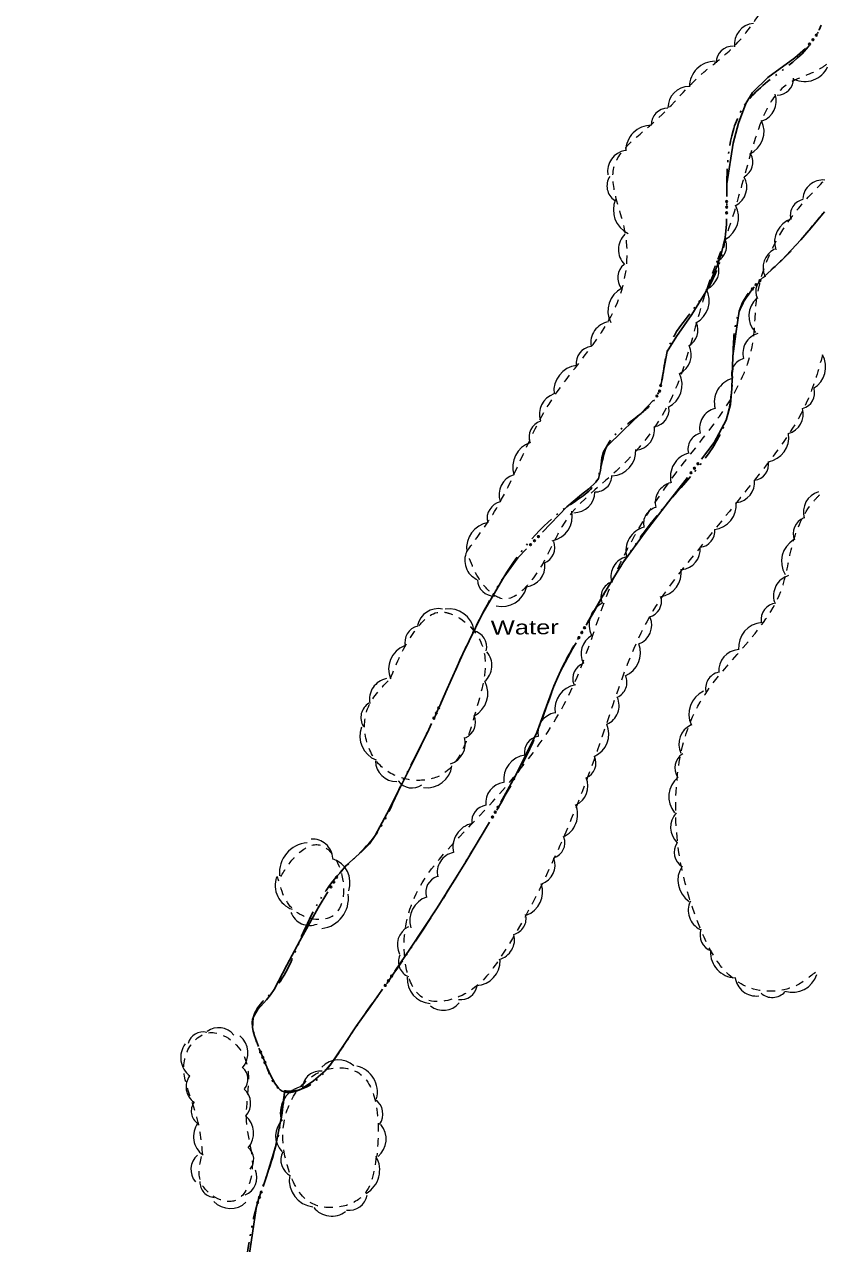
# Model space of a CAD drawing. Extents: x 2362213 to 2366494, y 6968794 to 6978110.
# Drawn here: x 2364792.2 to 2365065, y 6975207 to 6975621.3 of the extents above; entities that cross this region are included whole.
import ezdxf

# ---------------------------------------------------------------- set-up
doc = ezdxf.new("R2010")
doc.units = 0
doc.header["$LTSCALE"] = 1.9
doc.linetypes.add('DASH_DOUBLE_DOT', pattern=[9.2, 5, -1.2, 0.3, -1.2, 0.3, -1.2])
doc.linetypes.add('SHORT_DASHED', pattern=[2.7, 1.5, -1.2])
doc.layers.add('25', color=7, linetype='Continuous', lineweight=25)
doc.layers.add('29', color=7, linetype='Continuous', lineweight=13)

msp = doc.modelspace()

# ---------------------------------------------------------------- linework, layer by layer
at = {"layer": '25'}
for points in [[(2365062.159, 6975619.386), (2365062.179, 6975619.426), (2365062.824, 6975621.003)], [(2365030.754, 6975563.124), (2365030.785, 6975567.134), (2365032.914, 6975580.986), (2365034.719, 6975587.782), (2365037.275, 6975594.467), (2365039.461, 6975598.109), (2365044.721, 6975603.279), (2365053.929, 6975609.927), (2365057.559, 6975613.081)], [(2365063.918, 6975557.58), (2365059.963, 6975552.822), (2365055.907, 6975548.132), (2365052.74, 6975544.652), (2365049.512, 6975541.241), (2365045.805, 6975537.747), (2365043.516, 6975535.635)], [(2365008.698, 6975500.561), (2365010.567, 6975510.18), (2365013.638, 6975515.299), (2365018.948, 6975522.669), (2365023.703, 6975530.446), (2365027.589, 6975539.453), (2365029.115, 6975544.087), (2365030.22, 6975548.838), (2365030.676, 6975553.383), (2365030.688, 6975555.284)], [(2365038.15, 6975529.923), (2365037.734, 6975529.459), (2365036.07, 6975526.762), (2365035.028, 6975523.802), (2365033.801, 6975516.201), (2365032.883, 6975508.582), (2365032.438, 6975497.607), (2365031.979, 6975492.153), (2365030.53, 6975486.829), (2365026.542, 6975479.19), (2365022.186, 6975473.578)], [(2364968.18, 6975448.702), (2364976.487, 6975457.332), (2364981.428, 6975461.509), (2364983.96, 6975463.534), (2364986.299, 6975465.747), (2364987.147, 6975467.015), (2364987.871, 6975469.672), (2364988.35, 6975474.016), (2364988.871, 6975476.021), (2364989.925, 6975477.711), (2364995.562, 6975483.255), (2365001.239, 6975488.76), (2365004.092, 6975491.677), (2365005.755, 6975493.523)], [(2365017.385, 6975467.383), (2365010.924, 6975459.04), (2365003.08, 6975448.755), (2364995.481, 6975438.302), (2364988.882, 6975427.569), (2364983.443, 6975418.016)], [(2364933.728, 6975390.882), (2364935.394, 6975394.538), (2364941.102, 6975407.393), (2364947.566, 6975420.676), (2364954.993, 6975433.506), (2364959.782, 6975439.982), (2364962.744, 6975443.051)], [(2364979.567, 6975411.199), (2364978.387, 6975409.128), (2364974.299, 6975401.569), (2364972.048, 6975396.457), (2364966.278, 6975380.661), (2364959.182, 6975366.413), (2364954.022, 6975357.033)], [(2364899.448, 6975333.103), (2364901.544, 6975335.653), (2364906.879, 6975340.384), (2364909.374, 6975342.878), (2364911.387, 6975345.727), (2364915.258, 6975353.005), (2364918.989, 6975360.36), (2364924.308, 6975371.041), (2364929.566, 6975381.752), (2364930.476, 6975383.75)], [(2364950.157, 6975350.206), (2364942.136, 6975336.679), (2364932.402, 6975321.126), (2364923.393, 6975307.43), (2364918.028, 6975299.548)], [(2364871.699, 6975273.966), (2364870.354, 6975277.603), (2364869.879, 6975279.199), (2364869.637, 6975280.436), (2364869.569, 6975282.306), (2364869.711, 6975283.207), (2364870.003, 6975284.069), (2364871.499, 6975286.534), (2364874.379, 6975289.852), (2364875.783, 6975291.536), (2364876.975, 6975293.347), (2364881.327, 6975301.649), (2364885.717, 6975309.941), (2364891.991, 6975321.081), (2364895.241, 6975326.502)], [(2364913.599, 6975293.076), (2364909.602, 6975287.417), (2364905.015, 6975280.963), (2364900.754, 6975274.673), (2364896.504, 6975268.352), (2364894.318, 6975265.721), (2364890.4, 6975262.352), (2364886.187, 6975259.473), (2364884.316, 6975258.645), (2364882.689, 6975258.36), (2364881.469, 6975258.358), (2364879.765, 6975258.792), (2364879.041, 6975259.215), (2364878.445, 6975259.809), (2364877.238, 6975261.537), (2364875.782, 6975264.254), (2364874.679, 6975266.714)], [(2364873.302, 6975226.449), (2364874.44, 6975229.83), (2364877.525, 6975239.849), (2364879.267, 6975249.057), (2364880.589, 6975258.32)], [(2364854.508, 6975161.717), (2364855.095, 6975163.043), (2364864.662, 6975185.435), (2364867.142, 6975193.798), (2364870.952, 6975218.985)]]:
    msp.add_lwpolyline(points, dxfattribs=at)
for centre in [(2365058.871, 6975614.568), (2365060.028, 6975616.1), (2365061.185, 6975617.632), (2365030.737, 6975561.119), (2365030.707, 6975557.279), (2365030.722, 6975559.199), (2365040.768, 6975532.841), (2365042.05, 6975534.271), (2365039.487, 6975531.411), (2365008.312, 6975498.595), (2365007.04, 6975495.04), (2365007.945, 6975496.711), (2365019.785, 6975470.478), (2365020.961, 6975471.996), (2365018.609, 6975468.96), (2364964.127, 6975444.496), (2364965.459, 6975445.879), (2364966.79, 6975447.262), (2364982.456, 6975416.275), (2364980.557, 6975412.938), (2364981.507, 6975414.607), (2364932.101, 6975387.315), (2364932.897, 6975389.062), (2364931.304, 6975385.568), (2364952.127, 6975353.605), (2364953.054, 6975355.287), (2364951.184, 6975351.934), (2364897.257, 6975329.859), (2364898.244, 6975331.505), (2364896.27, 6975328.212), (2364915.828, 6975296.317), (2364916.908, 6975297.905), (2364914.749, 6975294.73), (2364872.41, 6975272.087), (2364873.153, 6975270.316), (2364873.896, 6975268.546), (2364871.431, 6975220.906), (2364872.044, 6975222.725), (2364872.657, 6975224.544)]:
    msp.add_circle(centre, 0.3, dxfattribs=at)
at = {"layer": '25', "linetype": 'DASH_DOUBLE_DOT'}
for points in [[(2365063.918, 6975557.58), (2365055.907, 6975548.132), (2365049.512, 6975541.241), (2365042.049, 6975534.271), (2365035.028, 6975523.802), (2365032.883, 6975508.582), (2365030.53, 6975486.829), (2365010.924, 6975459.04), (2364995.481, 6975438.302), (2364982.646, 6975416.609), (2364974.299, 6975401.569), (2364966.278, 6975380.661), (2364951.496, 6975352.46), (2364932.402, 6975321.126), (2364914.171, 6975293.881), (2364905.015, 6975280.963), (2364896.504, 6975268.352), (2364886.187, 6975259.473), (2364878.445, 6975259.809), (2364874.516, 6975267.072), (2364870.354, 6975277.603), (2364870.003, 6975284.069), (2364876.975, 6975293.347), (2364885.717, 6975309.941), (2364898.568, 6975332.044), (2364911.387, 6975345.727), (2364918.989, 6975360.36), (2364929.566, 6975381.752), (2364941.102, 6975407.393), (2364954.993, 6975433.506), (2364976.487, 6975457.332), (2364986.299, 6975465.747), (2364989.925, 6975477.711), (2365001.239, 6975488.76), (2365006.834, 6975494.713), (2365010.567, 6975510.18), (2365023.703, 6975530.446), (2365030.22, 6975548.838), (2365030.785, 6975567.134), (2365037.275, 6975594.467), (2365061.393, 6975617.909), (2365062.824, 6975621.003)], [(2364880.589, 6975258.32), (2364877.525, 6975239.849), (2364871.094, 6975219.908), (2364864.662, 6975185.435), (2364845.306, 6975140.768), (2364823.357, 6975091.227), (2364815.989, 6975073.156), (2364814.973, 6975063.335), (2364818.448, 6975044.908), (2364822.288, 6975034.333), (2364822.262, 6975003.553), (2364811.904, 6974962.381), (2364804.082, 6974926.715), (2364795.967, 6974870.495), (2364792.717, 6974825.452), (2364799.432, 6974783.884), (2364816.642, 6974732.655)]]:
    msp.add_spline(points, degree=3, dxfattribs=at)
at = {"layer": '29'}
for centre, radius, start, end in [((2365040.598, 6975614.444), 7.242, 96.26572, 186.26572), ((2365032.904, 6975608.141), 5.788, 88.54106, 178.54106), ((2365026.755, 6975600.07), 8.687, 89.65841, 179.65841), ((2365057.278, 6975610.435), 8.534, 245.10887, 335.10887), ((2365047.782, 6975602.902), 5.686, 270.75774, 0.75774), ((2365018.032, 6975593.007), 7.242, 90.77361, 180.77361), ((2365040.491, 6975595.256), 7.115, 289.02425, 19.02425), ((2365010.853, 6975587.1), 5.788, 90.77361, 180.77361), ((2365005.169, 6975578.343), 8.687, 90.04297, 180.04297), ((2365034.888, 6975584.973), 8.534, 295.20404, 25.20404), ((2364997.5, 6975571.343), 7.242, 99.50324, 189.50324), ((2365033.935, 6975574.443), 5.686, 299.00855, 29.00855), ((2364995.849, 6975566.415), 5.788, 146.59527, 236.59527), ((2365030.458, 6975566.062), 7.115, 298.29064, 28.29064), ((2365063.475, 6975561.517), 6.932, 85.01694, 175.01694), ((2365000.925, 6975558.158), 8.687, 155.44478, 245.44478), ((2365057.885, 6975556.413), 5.54, 101.85991, 191.85991), ((2365026.225, 6975555.775), 8.534, 298.29064, 28.29064), ((2365055.32, 6975547.325), 8.315, 108.31657, 198.31657), ((2365001.21, 6975544.813), 7.242, 134.27645, 224.27645), ((2365025.021, 6975545.954), 5.686, 295.16425, 25.16425), ((2365050.001, 6975538.654), 6.932, 115.79681, 205.79681), ((2365020.991, 6975537.763), 7.115, 295.10516, 25.10516), ((2364999.509, 6975535.237), 5.788, 128.90337, 218.90337), ((2365046.166, 6975530.624), 5.54, 115.79681, 205.79681), ((2364999.064, 6975523.928), 8.687, 117.22086, 207.22086), ((2365016.28, 6975527.415), 8.534, 297.62615, 27.62615), ((2365046.607, 6975522.195), 8.315, 132.47482, 222.47482), ((2364991.83, 6975513.103), 7.242, 100.11303, 190.11303), ((2365015.306, 6975517.259), 5.686, 297.62615, 27.62615), ((2365043.166, 6975509.571), 6.932, 105.13618, 195.13618), ((2364985.344, 6975506.074), 5.788, 96.68935, 186.68935), ((2365011.583, 6975509.002), 7.115, 296.65588, 26.65588), ((2365037.912, 6975502.39), 5.54, 105.13618, 195.13618), ((2365056.045, 6975504.874), 8.315, 299.95229, 29.95229), ((2364980.725, 6975496.773), 8.687, 96.68935, 186.68935), ((2365007.058, 6975498.84), 8.534, 296.65588, 26.65588), ((2365034.845, 6975492.934), 8.315, 105.13618, 195.13618), ((2364974.382, 6975488.861), 7.242, 108.67821, 198.67821), ((2365055.079, 6975496.139), 5.54, 285.19506, 15.19506), ((2365005.472, 6975490.313), 5.686, 277.69442, 7.69442), ((2365028.448, 6975484.093), 6.932, 104.38489, 194.38489), ((2365049.832, 6975488.952), 6.932, 285.19506, 15.19506), ((2364969.367, 6975481.034), 5.788, 108.67821, 198.67821), ((2364999.17, 6975483.702), 7.115, 277.69442, 7.69442), ((2365023.1, 6975476.981), 5.54, 104.38489, 194.38489), ((2365043.505, 6975480.929), 8.315, 278.86359, 8.86359), ((2364966.734, 6975470.921), 8.687, 108.035, 198.035), ((2364991.348, 6975476.394), 8.534, 273.11665, 3.11665), ((2365019.91, 6975467.566), 8.315, 104.38489, 194.38489), ((2365039.424, 6975471.865), 5.54, 278.86359, 8.86359), ((2364960.629, 6975461.384), 7.242, 108.035, 198.035), ((2364986.069, 6975468.095), 5.686, 269.35503, 359.35503), ((2365013.418, 6975458.833), 6.932, 103.98947, 193.98947), ((2365033.277, 6975465.701), 6.932, 276.12934, 6.12934), ((2364978.878, 6975462.494), 7.115, 269.12346, 359.12346), ((2365063.997, 6975455.578), 7.202, 106.47614, 196.47614), ((2364955.126, 6975453.408), 5.788, 102.73939, 192.73939), ((2365025.677, 6975457.98), 8.315, 276.04766, 6.04766), ((2364969.768, 6975454.198), 8.534, 281.48164, 11.48164), ((2365008.021, 6975451.758), 5.54, 103.98947, 193.98947), ((2365059.074, 6975448.239), 5.756, 111.84398, 201.84398), ((2364951.086, 6975443.452), 8.687, 98.8566, 188.8566), ((2365004.785, 6975442.368), 8.315, 104.09993, 194.09993), ((2365021.156, 6975449.128), 5.54, 276.04766, 6.04766), ((2364966.688, 6975443.571), 5.686, 291.17019, 21.17019), ((2365058.004, 6975438.788), 8.639, 120.62202, 210.62202), ((2364948.88, 6975439.157), 7.115, 155.14628, 245.14628), ((2365014.827, 6975442.955), 6.932, 275.28839, 5.28839), ((2364961.935, 6975437.27), 7.115, 276.12712, 6.12712), ((2364998.327, 6975433.659), 6.932, 104.09993, 194.09993), ((2364951.804, 6975432.689), 5.686, 180.99571, 270.99571), ((2365007.003, 6975435.03), 8.315, 278.26468, 8.26468), ((2365053.824, 6975427.094), 7.202, 107.0225, 197.0225), ((2364954.431, 6975432.02), 8.534, 256.62042, 346.62042), ((2364993.563, 6975426.636), 5.54, 109.22819, 199.22819), ((2364992.295, 6975417.287), 8.315, 115.99827, 205.99827), ((2365003.075, 6975425.302), 5.54, 284.93825, 14.93825), ((2365048.149, 6975418.948), 5.756, 97.41294, 187.41294), ((2364932.76, 6975415.596), 7.166, 78.09707, 168.09707), ((2364936.413, 6975414.084), 8.595, 9.05895, 99.05895), ((2364927.14, 6975411.271), 5.726, 103.70869, 193.70869), ((2364998.336, 6975417.196), 6.932, 292.00234, 22.00234), ((2365043.394, 6975409.438), 8.639, 94.32451, 184.32451), ((2364943.493, 6975409.7), 5.726, 347.59757, 77.59757), ((2364988.186, 6975407.48), 6.932, 118.01861, 208.01861), ((2364924.515, 6975402.209), 8.595, 112.26932, 202.26932), ((2364943.82, 6975403.411), 7.166, 310.84806, 40.84806), ((2364993.137, 6975407.683), 8.315, 292.00234, 22.00234), ((2365035.248, 6975401.663), 7.202, 94.32451, 184.32451), ((2364984.005, 6975399.015), 5.54, 110.57285, 200.57285), ((2364991.327, 6975397.734), 5.54, 294.07773, 24.07773), ((2365029.314, 6975395.588), 5.756, 103.83081, 193.83081), ((2364916.554, 6975391.963), 7.166, 101.08949, 191.08949), ((2364941.019, 6975394.009), 8.595, 297.08781, 27.08781), ((2364980.686, 6975388.63), 8.315, 99.26743, 189.26743), ((2364987.253, 6975389.823), 6.932, 294.07773, 24.07773), ((2365026.55, 6975386.888), 8.639, 115.18785, 205.18785), ((2364912.207, 6975385.779), 5.726, 121.76714, 211.76714), ((2364973.518, 6975380.496), 6.932, 99.26743, 189.26743), ((2364939.706, 6975384.158), 5.726, 293.31558, 23.31558), ((2364982.406, 6975380.154), 8.315, 293.8153, 23.8153), ((2365021.707, 6975376.722), 7.202, 115.18785, 205.18785), ((2364914.771, 6975379.37), 8.595, 159.01523, 249.01523), ((2364934.815, 6975376.924), 7.166, 286.91194, 16.91194), ((2364967.557, 6975373.889), 5.54, 99.26743, 189.26743), ((2364918.611, 6975371.16), 7.166, 180.81887, 270.81887), ((2364963.296, 6975364.726), 8.315, 97.32175, 187.32175), ((2364980.802, 6975370.344), 5.54, 293.8153, 23.8153), ((2365018.912, 6975368.624), 5.756, 122.89184, 212.89184), ((2364928.897, 6975370.506), 8.595, 262.47516, 352.47516), ((2364923.852, 6975367.568), 5.726, 215.65359, 305.65359), ((2364955.856, 6975356.841), 6.932, 97.32175, 187.32175), ((2364976.692, 6975362.452), 6.932, 293.8153, 23.8153), ((2365019.734, 6975358.857), 8.639, 129.25906, 219.25906), ((2364949.674, 6975350.44), 5.54, 97.32175, 187.32175), ((2364971.789, 6975352.788), 8.315, 293.75935, 23.75935), ((2364946.046, 6975341.653), 8.315, 102.46256, 192.46256), ((2365018.88, 6975348.443), 7.202, 136.84229, 226.84229), ((2364889.145, 6975332.912), 10.36, 94.9723, 184.9723), ((2364890.026, 6975337.581), 6.903, 3.50257, 93.50257), ((2364970.241, 6975343.277), 5.54, 289.35494, 19.35494), ((2365018.68, 6975339.979), 5.756, 146.56403, 236.56403), ((2364894.168, 6975329.604), 8.638, 341.74443, 71.74443), ((2364939.342, 6975333.132), 6.932, 102.46256, 192.46256), ((2364965.53, 6975335.729), 6.932, 289.35494, 19.35494), ((2365022.791, 6975330.506), 8.639, 146.56403, 236.56403), ((2364886.002, 6975328.755), 8.638, 160.79763, 250.79763), ((2364934.072, 6975326.413), 5.54, 107.42253, 197.42253), ((2364959.897, 6975326.465), 8.315, 289.35494, 19.35494), ((2364891.887, 6975324.332), 10.36, 277.56268, 7.56268), ((2364931.385, 6975316.842), 8.315, 107.42253, 197.42253), ((2365024.876, 6975320.251), 7.202, 154.10605, 244.10605), ((2364889.138, 6975322.034), 6.903, 201.27127, 291.27127), ((2364957.07, 6975317.426), 5.54, 284.56735, 14.56735), ((2364925.797, 6975308.524), 6.932, 117.16182, 207.16182), ((2365027.434, 6975311.921), 5.756, 160.34874, 250.34874), ((2364951.744, 6975310.297), 6.932, 284.56735, 14.56735), ((2364924.767, 6975302.826), 5.54, 157.155, 247.155), ((2365033.88, 6975305.973), 8.639, 177.68723, 267.68723), ((2364945.466, 6975303.032), 8.315, 272.17382, 2.17382), ((2364930.536, 6975296.936), 8.315, 176.04946, 266.04946), ((2365040.811, 6975298.34), 7.202, 186.85135, 276.85135), ((2365053.056, 6975301.014), 8.639, 253.01183, 343.01183), ((2364940.465, 6975295.447), 5.54, 261.39497, 351.39497), ((2365046.225, 6975296.397), 5.756, 228.29072, 318.29072), ((2364934.507, 6975293.178), 6.932, 230.6227, 320.6227), ((2364858.171, 6975273.937), 6.443, 37.5506, 127.5506), ((2364852.85, 6975273.791), 5.149, 75.91621, 165.91621), ((2364860.357, 6975271.739), 7.728, 319.62896, 49.62896), ((2364853.019, 6975270.252), 7.728, 143.51154, 233.51154), ((2364862.985, 6975262.881), 5.149, 319.62896, 49.62896), ((2364898.832, 6975261.782), 7.661, 47.03428, 137.03428), ((2364902.91, 6975258.432), 9.189, 346.00815, 76.00815), ((2364853.537, 6975260.285), 6.443, 144.58354, 234.58354), ((2364892.711, 6975259.531), 6.122, 84.02604, 174.02604), ((2364862.61, 6975254.706), 6.443, 318.35848, 48.35848), ((2364888.269, 6975251.376), 9.189, 101.40017, 191.40017), ((2364854.007, 6975252.028), 5.149, 144.58354, 234.58354), ((2364907.828, 6975251.021), 6.122, 324.84147, 54.84147), ((2364862.311, 6975244.51), 7.728, 319.84036, 49.84036), ((2364857.361, 6975243.411), 7.728, 144.42874, 234.42874), ((2364885.189, 6975243.586), 7.661, 133.79395, 223.79395), ((2364907.395, 6975242.507), 7.661, 309.96301, 39.96301), ((2364864.942, 6975235.694), 5.149, 319.30557, 49.30557), ((2364885.403, 6975235.459), 6.122, 153.08088, 243.08088), ((2364855.192, 6975232.141), 6.443, 130.28145, 220.28145), ((2364903.685, 6975232.019), 9.189, 300.31809, 30.31809), ((2364864.731, 6975229.537), 6.443, 292.25491, 22.25491), ((2364891.319, 6975228.599), 9.189, 172.49239, 262.49239), ((2364856.947, 6975227.84), 5.149, 177.23018, 267.23018), ((2364862.122, 6975226.664), 7.728, 223.63648, 313.63648), ((2364902.565, 6975224.455), 6.122, 260.87131, 350.87131), ((2364896.562, 6975223.986), 7.661, 217.69913, 307.69913)]:
    msp.add_arc(centre, radius, start, end, dxfattribs=at)
at = {"layer": '29', "linetype": 'SHORT_DASHED'}
for points in [[(2364942.441, 6975442.158), (2364953.102, 6975457.839), (2364970.395, 6975492.307), (2364992.972, 6975525.292), (2364996.187, 6975551.034), (2364992.595, 6975573.251), (2365006.61, 6975588.585), (2365023.082, 6975605.183), (2365028.293, 6975609.383), (2365036.447, 6975617.42), (2365049.354, 6975633.395), (2365062.836, 6975640.764)], [(2365064.631, 6975607.649), (2365062.057, 6975605.985), (2365051.653, 6975601.135), (2365040.1, 6975581.414), (2365031.518, 6975552.161), (2365023.352, 6975529.563), (2365012.066, 6975494.532), (2364994.333, 6975470.573), (2364976.328, 6975453.04), (2364964.07, 6975431.933), (2364954.854, 6975426.085), (2364948.999, 6975429.829), (2364942.441, 6975442.158)], [(2365063.32, 6975509.012), (2365058.52, 6975494.296), (2365041.736, 6975468.415), (2365021.504, 6975443.351), (2365005.696, 6975422.039), (2364988.374, 6975379.082), (2364974.084, 6975342.264), (2364953.56, 6975303.747), (2364943.533, 6975292.861), (2364928.771, 6975289.9), (2364921.217, 6975310.229), (2364943.876, 6975349.317), (2364977.823, 6975394.842), (2364992.556, 6975433.524), (2365014.479, 6975470.075), (2365039.669, 6975513.287), (2365040.875, 6975527.298), (2365053.228, 6975556.418), (2365064.045, 6975568.371)], [(2365060.858, 6975299.168), (2365053.983, 6975294.503), (2365037.945, 6975294.14), (2365020.884, 6975316.278), (2365013.481, 6975358.48), (2365020.955, 6975389.602), (2365049.621, 6975429.997), (2365053.113, 6975444.612), (2365060.126, 6975459.078), (2365062.749, 6975461.894)], [(2364916.49, 6975398.979), (2364924.66, 6975414.957), (2364933.745, 6975421.634), (2364936.721, 6975421.083), (2364947.225, 6975411.351), (2364945.401, 6975387.563), (2364932.847, 6975365.782), (2364914.01, 6975368.593), (2364908.758, 6975388.734), (2364915.916, 6975398.404)], [(2364879.25, 6975331.7), (2364884.185, 6975338.538), (2364891.136, 6975342.594), (2364900.278, 6975331.001), (2364896.382, 6975318.003), (2364884.333, 6975319.848), (2364878.17, 6975331.73)], [(2364852.8, 6975237.114), (2364850.539, 6975250.783), (2364847.22, 6975271.623), (2364854.335, 6975278.571), (2364865.854, 6975272.39), (2364867.509, 6975248.675), (2364869.076, 6975229.089), (2364863.577, 6975221.576), (2364852.25, 6975227.619), (2364852.395, 6975236.61)], [(2364911.696, 6975236.645), (2364906.877, 6975222.988), (2364889.696, 6975220.745), (2364882.35, 6975230.915), (2364882.012, 6975253.843), (2364895.673, 6975266.404), (2364906.29, 6975264.615), (2364911.744, 6975253.676), (2364911.895, 6975236.727)]]:
    msp.add_spline(points, degree=3, dxfattribs=at)

# ---------------------------------------------------------------- texts
at = {"layer": '25', "width": 1.35}
msp.add_text('Water', height=4.8, rotation=0.546, dxfattribs=at).set_placement((2364950.621, 6975413.904))

doc.saveas('drawing.dxf')
